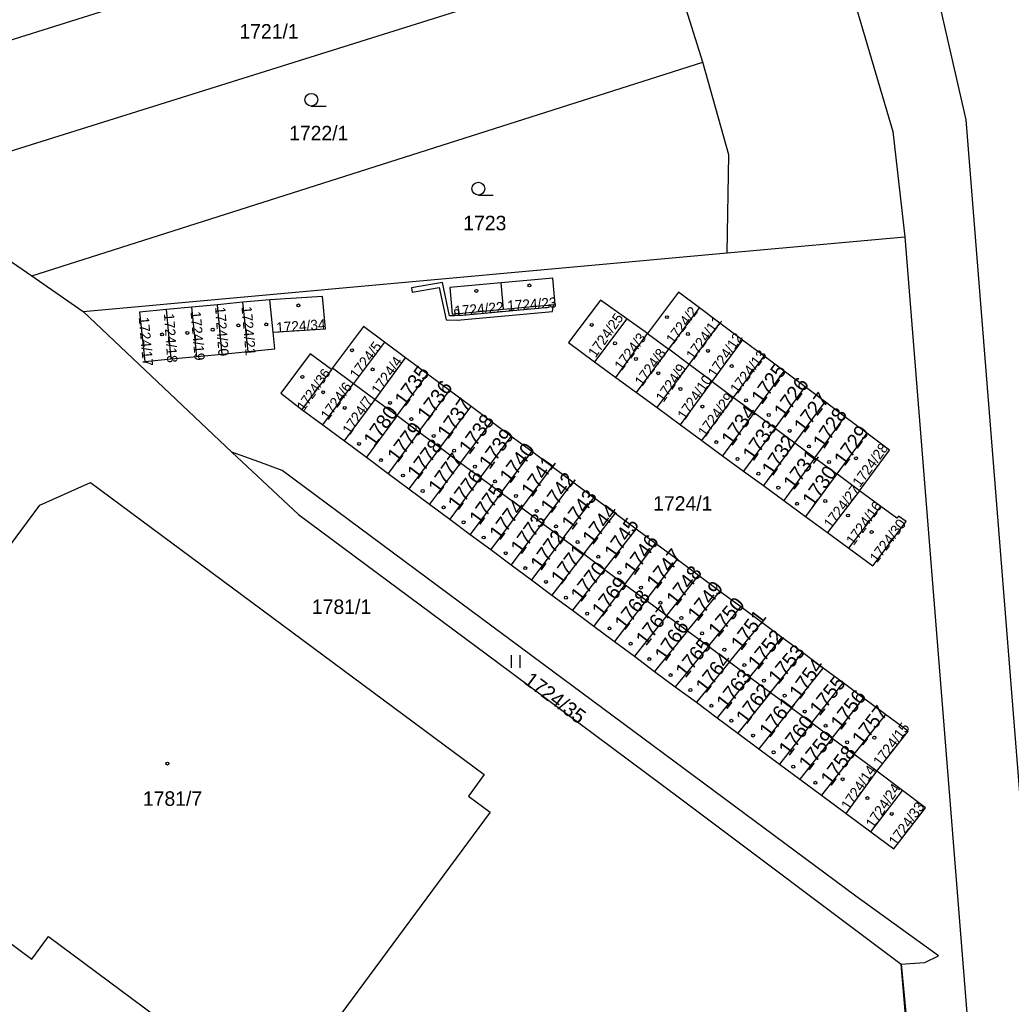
# Model space of a CAD drawing. Extents: x -756746 to -753363, y -1166406 to -1161727.
# Drawn here: x -755865.5 to -755749.2, y -1163941.9 to -1163826.4 of the extents above; entities that cross this region are included whole.
import ezdxf

# ---------------------------------------------------------------- set-up
doc = ezdxf.new("R2010")
doc.units = 0
for name, color, linetype in [('Hranice parcel', 7, 'Continuous'), ('Parcelní čísla', 7, 'Continuous'), ('Věcná břemena k části', 7, 'Continuous'), ('Značky budov', 7, 'Continuous'), ('Značky kultur', 7, 'Continuous')]:
    doc.layers.add(name, color=color, linetype=linetype)

msp = doc.modelspace()

# ---------------------------------------------------------------- linework, layer by layer
at = {"layer": 'Hranice parcel'}
for p, q in [((-755892.36, -1163836.88), (-755793.46, -1163805.8)), ((-755879.46, -1163845.82), (-755796.98, -1163819.99)), ((-755785.34, -1163831.39), (-755788.73, -1163820.69)), ((-755864.11, -1163856.44), (-755785.34, -1163831.39)), ((-755879.46, -1163845.82), (-755864.11, -1163856.44)), ((-755782.49, -1163853.74), (-755761.66, -1163851.85)), ((-755858.09, -1163860.61), (-755782.49, -1163853.74)), ((-755864.11, -1163856.44), (-755858.09, -1163860.61)), ((-755808.73, -1163860.37), (-755809.02, -1163857.25)), ((-755836.15, -1163859.25), (-755839.32, -1163859.55)), ((-755835.77, -1163863.05), (-755836.15, -1163859.25)), ((-755840.62, -1163877.14), (-755858.09, -1163860.61)), ((-755845.31, -1163860.12), (-755848.31, -1163860.41)), ((-755847.74, -1163866.18), (-755848.31, -1163860.41)), ((-755842.32, -1163859.84), (-755845.31, -1163860.12)), ((-755844.75, -1163865.89), (-755845.31, -1163860.12)), ((-755839.32, -1163859.55), (-755842.32, -1163859.84)), ((-755841.78, -1163865.61), (-755842.32, -1163859.84)), ((-755838.72, -1163865.32), (-755839.32, -1163859.55)), ((-755789.36, -1163865.04), (-755785.76, -1163860.2)), ((-755783.36, -1163861.99), (-755785.76, -1163860.2)), ((-755794.29, -1163861.47), (-755798.07, -1163866.51)), ((-755791.84, -1163863.2), (-755794.29, -1163861.47)), ((-755786.96, -1163866.83), (-755783.36, -1163861.99)), ((-755780.7, -1163863.97), (-755783.36, -1163861.99)), ((-755795.57, -1163868.35), (-755791.84, -1163863.2)), ((-755791.84, -1163863.2), (-755789.36, -1163865.04)), ((-755784.26, -1163868.83), (-755780.7, -1163863.97)), ((-755778.16, -1163865.88), (-755780.7, -1163863.97)), ((-755841.78, -1163865.61), (-755838.72, -1163865.32)), ((-755822.73, -1163864.22), (-755826.34, -1163869.06)), ((-755820.25, -1163866.06), (-755822.73, -1163864.22)), ((-755793.14, -1163870.13), (-755789.36, -1163865.04)), ((-755786.96, -1163866.83), (-755789.36, -1163865.04)), ((-755847.74, -1163866.18), (-755844.75, -1163865.89)), ((-755844.75, -1163865.89), (-755841.78, -1163865.61)), ((-755823.82, -1163870.93), (-755820.25, -1163866.06)), ((-755817.66, -1163867.98), (-755820.25, -1163866.06)), ((-755798.07, -1163866.51), (-755795.57, -1163868.35)), ((-755781.74, -1163870.7), (-755778.16, -1163865.88)), ((-755775.8, -1163867.64), (-755778.16, -1163865.88)), ((-755828.94, -1163867.42), (-755832.41, -1163872.1)), ((-755828.8, -1163867.24), (-755828.94, -1163867.42)), ((-755828.8, -1163867.24), (-755826.34, -1163869.06)), ((-755790.73, -1163871.9), (-755786.96, -1163866.83)), ((-755784.26, -1163868.83), (-755786.96, -1163866.83)), ((-755779.34, -1163872.48), (-755775.8, -1163867.64)), ((-755773.34, -1163869.48), (-755775.8, -1163867.64)), ((-755821.24, -1163872.84), (-755817.66, -1163867.98)), ((-755815.08, -1163869.89), (-755817.66, -1163867.98)), ((-755795.57, -1163868.35), (-755793.14, -1163870.13)), ((-755787.99, -1163873.91), (-755784.26, -1163868.83)), ((-755784.26, -1163868.83), (-755781.74, -1163870.7)), ((-755829.96, -1163873.92), (-755826.34, -1163869.06)), ((-755826.34, -1163869.06), (-755823.82, -1163870.93)), ((-755818.68, -1163874.74), (-755815.08, -1163869.89)), ((-755812.54, -1163871.78), (-755815.08, -1163869.89)), ((-755776.88, -1163874.31), (-755773.34, -1163869.48)), ((-755771.01, -1163871.22), (-755773.34, -1163869.48)), ((-755827.41, -1163875.81), (-755823.82, -1163870.93)), ((-755823.82, -1163870.93), (-755821.24, -1163872.84)), ((-755793.14, -1163870.13), (-755790.73, -1163871.9)), ((-755785.49, -1163875.74), (-755781.74, -1163870.7)), ((-755781.74, -1163870.7), (-755779.34, -1163872.48)), ((-755832.41, -1163872.1), (-755829.96, -1163873.92)), ((-755816.18, -1163876.58), (-755812.54, -1163871.78)), ((-755810.15, -1163873.55), (-755812.54, -1163871.78)), ((-755790.73, -1163871.9), (-755787.99, -1163873.91)), ((-755774.55, -1163876.03), (-755771.01, -1163871.22)), ((-755768.68, -1163872.96), (-755771.01, -1163871.22)), ((-755821.24, -1163872.84), (-755824.84, -1163877.72)), ((-755821.24, -1163872.84), (-755818.68, -1163874.74)), ((-755779.34, -1163872.48), (-755783.04, -1163877.54)), ((-755779.34, -1163872.48), (-755776.88, -1163874.31)), ((-755772.2, -1163877.78), (-755768.68, -1163872.96)), ((-755766.1, -1163874.89), (-755768.68, -1163872.96)), ((-755829.96, -1163873.92), (-755827.41, -1163875.81)), ((-755813.78, -1163878.36), (-755810.15, -1163873.55)), ((-755807.83, -1163875.27), (-755810.15, -1163873.55)), ((-755787.99, -1163873.91), (-755785.49, -1163875.74)), ((-755776.88, -1163874.31), (-755780.57, -1163879.35)), ((-755776.88, -1163874.31), (-755774.55, -1163876.03)), ((-755827.41, -1163875.81), (-755824.84, -1163877.72)), ((-755818.68, -1163874.74), (-755822.29, -1163879.61)), ((-755818.68, -1163874.74), (-755816.18, -1163876.58)), ((-755811.43, -1163880.11), (-755807.83, -1163875.27)), ((-755805.44, -1163877.05), (-755807.83, -1163875.27)), ((-755785.49, -1163875.74), (-755783.04, -1163877.54)), ((-755766.1, -1163874.89), (-755769.64, -1163879.68)), ((-755816.18, -1163876.58), (-755819.85, -1163881.42)), ((-755816.18, -1163876.58), (-755813.78, -1163878.36)), ((-755774.55, -1163876.03), (-755778.25, -1163881.05)), ((-755774.55, -1163876.03), (-755772.2, -1163877.78)), ((-755824.84, -1163877.72), (-755822.29, -1163879.61)), ((-755809.03, -1163881.88), (-755805.44, -1163877.05)), ((-755803.02, -1163878.85), (-755805.44, -1163877.05)), ((-755783.04, -1163877.54), (-755780.57, -1163879.35)), ((-755772.2, -1163877.78), (-755775.87, -1163882.79)), ((-755772.2, -1163877.78), (-755769.64, -1163879.68)), ((-755813.78, -1163878.36), (-755817.44, -1163883.21)), ((-755813.78, -1163878.36), (-755811.43, -1163880.11)), ((-755806.61, -1163883.67), (-755803.02, -1163878.85)), ((-755800.6, -1163880.64), (-755803.02, -1163878.85)), ((-755822.29, -1163879.61), (-755819.85, -1163881.42)), ((-755811.43, -1163880.11), (-755815.05, -1163884.98)), ((-755811.43, -1163880.11), (-755809.03, -1163881.88)), ((-755780.57, -1163879.35), (-755778.25, -1163881.05)), ((-755769.64, -1163879.68), (-755773.32, -1163884.67)), ((-755766.99, -1163881.65), (-755769.64, -1163879.68)), ((-755819.85, -1163881.42), (-755817.44, -1163883.21)), ((-755804.2, -1163885.46), (-755800.6, -1163880.64)), ((-755798.13, -1163882.48), (-755800.6, -1163880.64)), ((-755778.25, -1163881.05), (-755775.87, -1163882.79)), ((-755809.03, -1163881.88), (-755812.66, -1163886.76)), ((-755809.03, -1163881.88), (-755806.61, -1163883.67)), ((-755801.78, -1163887.25), (-755798.13, -1163882.48)), ((-755795.65, -1163884.31), (-755798.13, -1163882.48)), ((-755775.87, -1163882.79), (-755773.32, -1163884.67)), ((-755766.99, -1163881.65), (-755770.74, -1163886.56)), ((-755764.48, -1163883.48), (-755766.99, -1163881.65)), ((-755817.44, -1163883.21), (-755815.05, -1163884.98)), ((-755806.61, -1163883.67), (-755810.25, -1163888.55)), ((-755806.61, -1163883.67), (-755804.2, -1163885.46)), ((-755768.24, -1163888.39), (-755764.48, -1163883.48)), ((-755815.05, -1163884.98), (-755812.66, -1163886.76)), ((-755799.33, -1163889.06), (-755795.65, -1163884.31)), ((-755793.19, -1163886.15), (-755795.65, -1163884.31)), ((-755773.32, -1163884.67), (-755770.74, -1163886.56)), ((-755804.2, -1163885.46), (-755807.85, -1163890.33)), ((-755804.2, -1163885.46), (-755801.78, -1163887.25)), ((-755796.9, -1163890.87), (-755793.19, -1163886.15)), ((-755790.92, -1163887.83), (-755793.19, -1163886.15)), ((-755812.66, -1163886.76), (-755810.25, -1163888.55)), ((-755801.78, -1163887.25), (-755805.48, -1163892.09)), ((-755801.78, -1163887.25), (-755799.33, -1163889.06)), ((-755770.74, -1163886.56), (-755768.24, -1163888.39)), ((-755810.25, -1163888.55), (-755807.85, -1163890.33)), ((-755794.51, -1163892.64), (-755790.92, -1163887.83)), ((-755788.35, -1163889.73), (-755790.92, -1163887.83)), ((-755799.33, -1163889.06), (-755803.07, -1163893.88)), ((-755799.33, -1163889.06), (-755796.9, -1163890.87)), ((-755792.01, -1163894.48), (-755788.35, -1163889.73)), ((-755785.88, -1163891.57), (-755788.35, -1163889.73)), ((-755807.85, -1163890.33), (-755805.48, -1163892.09)), ((-755796.9, -1163890.87), (-755800.67, -1163895.66)), ((-755796.9, -1163890.87), (-755794.51, -1163892.64)), ((-755805.48, -1163892.09), (-755803.07, -1163893.88)), ((-755789.6, -1163896.27), (-755785.88, -1163891.57)), ((-755783.35, -1163893.45), (-755785.88, -1163891.57)), ((-755794.51, -1163892.64), (-755798.16, -1163897.52)), ((-755794.51, -1163892.64), (-755792.01, -1163894.48)), ((-755803.07, -1163893.88), (-755800.67, -1163895.66)), ((-755787.14, -1163898.09), (-755783.35, -1163893.45)), ((-755780.91, -1163895.26), (-755783.35, -1163893.45)), ((-755792.01, -1163894.48), (-755795.74, -1163899.32)), ((-755792.01, -1163894.48), (-755789.6, -1163896.27)), ((-755784.71, -1163899.89), (-755780.91, -1163895.26)), ((-755778.42, -1163897.11), (-755780.91, -1163895.26)), ((-755800.67, -1163895.66), (-755798.16, -1163897.52)), ((-755789.6, -1163896.27), (-755793.39, -1163901.06)), ((-755789.6, -1163896.27), (-755787.14, -1163898.09)), ((-755798.16, -1163897.52), (-755795.74, -1163899.32)), ((-755782.23, -1163901.73), (-755778.42, -1163897.11)), ((-755776.08, -1163898.85), (-755778.42, -1163897.11)), ((-755787.14, -1163898.09), (-755791.01, -1163902.83)), ((-755787.14, -1163898.09), (-755784.71, -1163899.89)), ((-755779.83, -1163903.51), (-755776.08, -1163898.85)), ((-755773.68, -1163900.63), (-755776.08, -1163898.85)), ((-755795.74, -1163899.32), (-755793.39, -1163901.06)), ((-755784.71, -1163899.89), (-755788.59, -1163904.63)), ((-755784.71, -1163899.89), (-755782.23, -1163901.73)), ((-755793.39, -1163901.06), (-755791.01, -1163902.83)), ((-755777.42, -1163905.29), (-755773.68, -1163900.63)), ((-755771.23, -1163902.45), (-755773.68, -1163900.63)), ((-755782.23, -1163901.73), (-755786.12, -1163906.46)), ((-755782.23, -1163901.73), (-755779.83, -1163903.51)), ((-755774.96, -1163907.12), (-755771.23, -1163902.45)), ((-755768.89, -1163904.18), (-755771.23, -1163902.45)), ((-755791.01, -1163902.83), (-755788.59, -1163904.63)), ((-755779.83, -1163903.51), (-755783.67, -1163908.28)), ((-755779.83, -1163903.51), (-755777.42, -1163905.29)), ((-755788.59, -1163904.63), (-755786.12, -1163906.46)), ((-755772.57, -1163908.88), (-755768.89, -1163904.18)), ((-755766.49, -1163905.96), (-755768.89, -1163904.18)), ((-755777.42, -1163905.29), (-755781.26, -1163910.07)), ((-755777.42, -1163905.29), (-755774.96, -1163907.12)), ((-755770.18, -1163910.65), (-755766.49, -1163905.96)), ((-755763.93, -1163907.87), (-755766.49, -1163905.96)), ((-755786.12, -1163906.46), (-755783.67, -1163908.28)), ((-755774.96, -1163907.12), (-755778.78, -1163911.91)), ((-755774.96, -1163907.12), (-755772.57, -1163908.88)), ((-755783.67, -1163908.28), (-755781.26, -1163910.07)), ((-755763.93, -1163907.87), (-755767.63, -1163912.54)), ((-755772.57, -1163908.88), (-755776.35, -1163913.71)), ((-755772.57, -1163908.88), (-755770.18, -1163910.65)), ((-755781.26, -1163910.07), (-755778.78, -1163911.91)), ((-755770.18, -1163910.65), (-755773.97, -1163915.47)), ((-755770.18, -1163910.65), (-755767.63, -1163912.54)), ((-755778.78, -1163911.91), (-755776.35, -1163913.71)), ((-755767.63, -1163912.54), (-755771.44, -1163917.36)), ((-755764.92, -1163914.55), (-755767.63, -1163912.54)), ((-755776.35, -1163913.71), (-755773.97, -1163915.47)), ((-755768.55, -1163919.5), (-755764.92, -1163914.55)), ((-755761.92, -1163916.81), (-755764.92, -1163914.55)), ((-755773.97, -1163915.47), (-755771.44, -1163917.36)), ((-755771.44, -1163917.36), (-755768.55, -1163919.5)), ((-755765.66, -1163921.64), (-755761.92, -1163916.81)), ((-755768.55, -1163919.5), (-755765.66, -1163921.64)), ((-755756.36, -1164005.31), (-755762.08, -1163937.18)), ((-755762.08, -1163937.18), (-755753.77, -1164024.87))]:
    msp.add_line(p, q, dxfattribs=at)
for points in [[(-755791.86, -1163751.01), (-755779.82, -1163784.88), (-755772.62, -1163807.19), (-755763.05, -1163839.53), (-755761.66, -1163851.85)], [(-755745.81, -1163946.5), (-755754.44, -1163838.14), (-755759.37, -1163816.57)], [(-755782.49, -1163853.74), (-755782.31, -1163842.27), (-755785.34, -1163831.39)], [(-755761.66, -1163851.85), (-755753.95, -1163948.32), (-755749.42, -1164027.4)], [(-755808.73, -1163860.37), (-755802.68, -1163859.81), (-755802.97, -1163856.7), (-755809.02, -1163857.25)], [(-755809.02, -1163857.25), (-755815.06, -1163857.8), (-755814.78, -1163860.92), (-755808.73, -1163860.37)], [(-755785.76, -1163860.2), (-755788.23, -1163858.35), (-755791.84, -1163863.2)], [(-755835.77, -1163863.05), (-755829.65, -1163862.64), (-755829.97, -1163858.87), (-755836.15, -1163859.25)], [(-755794.29, -1163861.47), (-755797.38, -1163859.28), (-755801.13, -1163864.27), (-755798.07, -1163866.51)], [(-755848.31, -1163860.41), (-755851.47, -1163860.71), (-755850.82, -1163866.47), (-755847.74, -1163866.18)], [(-755822.73, -1163864.22), (-755825.19, -1163862.39), (-755828.8, -1163867.24)], [(-755838.72, -1163865.32), (-755835.58, -1163865.02), (-755835.77, -1163863.05)], [(-755828.94, -1163867.42), (-755831.42, -1163865.59), (-755834.87, -1163870.21), (-755832.41, -1163872.1)], [(-755766.99, -1163881.65), (-755763.45, -1163876.87), (-755766.1, -1163874.89)], [(-755840.62, -1163877.14), (-755832.8, -1163884.43), (-755809.43, -1163901.79), (-755788.08, -1163917.68), (-755762.08, -1163937.18)], [(-755762.08, -1163937.18), (-755761.07, -1163937.11), (-755759.29, -1163936.96), (-755757.71, -1163936.19), (-755767.42, -1163929.2), (-755812.53, -1163895.72), (-755834.74, -1163879.26), (-755837.47, -1163878.24), (-755840.62, -1163877.14)], [(-755889.91, -1163898.92), (-755889.22, -1163898), (-755894.17, -1163894.29), (-755889.13, -1163887.57), (-755874.43, -1163898.52), (-755863.15, -1163883.34), (-755857.21, -1163880.69), (-755811.01, -1163914.93), (-755812.86, -1163917.45), (-755810.31, -1163919.33), (-755827.83, -1163943.04), (-755807.18, -1163958.32), (-755817.15, -1163971.58), (-755812.4, -1163975.09), (-755813.9, -1163977.11)], [(-755768.24, -1163888.39), (-755765.41, -1163890.46), (-755761.5, -1163885.26), (-755762.41, -1163884.61), (-755762.58, -1163884.85), (-755764.48, -1163883.48)], [(-755889.91, -1163898.92), (-755898.81, -1163910.83), (-755864.1, -1163936.57), (-755862.15, -1163933.94), (-755838.26, -1163951.69), (-755835.8, -1163948.4), (-755833.21, -1163950.32), (-755839.11, -1163958.32), (-755813.9, -1163977.11)], [(-755764.92, -1163914.55), (-755761.26, -1163909.85), (-755763.93, -1163907.87)], [(-755765.66, -1163921.64), (-755762.96, -1163923.65), (-755759.21, -1163918.85), (-755761.92, -1163916.81)]]:
    msp.add_lwpolyline(points, dxfattribs=at)
at = {"layer": 'Věcná břemena k části'}
for points in [[(-755819.55, -1163857.85), (-755819.47, -1163858.34), (-755816.29, -1163857.81), (-755815.49, -1163861.6), (-755814.18, -1163861.64), (-755802.98, -1163860.63), (-755802.9, -1163859.83), (-755803.41, -1163859.88), (-755803.44, -1163860.17), (-755813.95, -1163861.12), (-755813.96, -1163860.85), (-755814.46, -1163860.89), (-755814.45, -1163861.13), (-755815.09, -1163861.12), (-755815.89, -1163857.23)], [(-755814.48, -1163860.46), (-755814.46, -1163860.89), (-755813.96, -1163860.85), (-755813.98, -1163860.42)]]:
    msp.add_lwpolyline(points, close=True, dxfattribs=at)
at = {"layer": 'Značky budov'}
for centre in [(-755811.93, -1163858.21), (-755805.7, -1163857.57), (-755832.81, -1163859.91), (-755789.58, -1163861.29), (-755845.85, -1163863.13), (-755842.87, -1163862.76), (-755839.86, -1163862.26), (-755836.59, -1163862.14), (-755798.39, -1163862.2), (-755848.81, -1163863.31), (-755795.67, -1163864.36), (-755787.11, -1163863.27), (-755826.52, -1163865.17), (-755784.76, -1163865.25), (-755793.21, -1163866.19), (-755824.11, -1163867.42), (-755781.97, -1163867.03), (-755832.35, -1163868.3), (-755790.59, -1163867.87), (-755829.91, -1163870.09), (-755787.98, -1163869.71), (-755822.06, -1163871.34), (-755780.28, -1163871.05), (-755827.37, -1163871.93), (-755785.4, -1163871.77), (-755819.56, -1163873.25), (-755777.62, -1163872.76), (-755775.16, -1163874.63), (-755816.94, -1163875.22), (-755783.79, -1163875.94), (-755825.69, -1163876.15), (-755814.55, -1163876.95), (-755772.91, -1163876.45), (-755823.14, -1163878.06), (-755781.29, -1163877.92), (-755770.54, -1163878.28), (-755767.38, -1163877.83), (-755812.11, -1163878.82), (-755820.55, -1163879.86), (-755809.73, -1163880.55), (-755778.83, -1163879.65), (-755818.23, -1163881.68), (-755776.5, -1163881.28), (-755807.29, -1163882.26), (-755771, -1163882.85), (-755815.77, -1163883.6), (-755804.86, -1163884.01), (-755774.3, -1163883.17), (-755768.34, -1163884.55), (-755813.43, -1163885.35), (-755802.59, -1163885.83), (-755811.07, -1163887.13), (-755765.55, -1163886.5), (-755800.06, -1163887.66), (-755808.48, -1163888.97), (-755797.63, -1163889.39), (-755806.2, -1163890.72), (-755795.15, -1163891.27), (-755803.77, -1163892.34), (-755792.61, -1163893), (-755801.43, -1163894.19), (-755790.33, -1163894.78), (-755798.93, -1163896.06), (-755787.88, -1163896.57), (-755796.31, -1163897.79), (-755785.44, -1163898.37), (-755793.83, -1163899.59), (-755782.83, -1163900.28), (-755791.65, -1163901.39), (-755780.49, -1163902.1), (-755789.15, -1163903.27), (-755778.19, -1163903.92), (-755786.81, -1163905.02), (-755775.76, -1163905.68), (-755784.35, -1163906.86), (-755773.39, -1163907.54), (-755782.01, -1163908.63), (-755770.96, -1163909.21), (-755779.46, -1163910.36), (-755765.23, -1163910.6), (-755768.43, -1163911.15), (-755777.05, -1163912.32), (-755848.18, -1163913.64), (-755774.75, -1163914.01), (-755768.96, -1163915.48), (-755772.14, -1163915.89), (-755766.04, -1163917.69), (-755763.18, -1163919.55)]:
    msp.add_circle(centre, 0.175, dxfattribs=at)
at = {"layer": 'Značky kultur'}
for p, q in [((-755831.3, -1163836.54), (-755829.55, -1163836.54)), ((-755811.7, -1163846.97), (-755809.95, -1163846.97)), ((-755807.8, -1163902.43), (-755807.8, -1163900.93)), ((-755806.8, -1163902.43), (-755806.8, -1163900.93))]:
    msp.add_line(p, q, dxfattribs=at)
for centre in [(-755831.3, -1163835.79), (-755811.7, -1163846.22)]:
    msp.add_circle(centre, 0.75, dxfattribs=at)

# ---------------------------------------------------------------- texts
at = {"layer": 'Parcelní čísla'}
for s, p in [('1721/1', (-755839.74, -1163828.62)), ('1722/1', (-755833.91, -1163840.55)), ('1723', (-755813.47, -1163851.1)), ('1724/1', (-755791.19, -1163883.99)), ('1781/1', (-755831.23, -1163896.1)), ('1781/7', (-755851.06, -1163918.6))]:
    msp.add_text(s, height=1.7, dxfattribs=at).set_placement(p)
for s, height, rotation, p in [('1724/22', 1.2, 5, (-755814.46, -1163861.18)), ('1724/23', 1.2, 4, (-755808.27, -1163860.56)), ('1724/20', 1.2, 274, (-755842.59, -1163860.11)), ('1724/21', 1.2, 275, (-755839.5, -1163860.06)), ('1724/2', 1.2, 53, (-755788.82, -1163864.54)), ('1724/17', 1.2, 275, (-755851.56, -1163861.31)), ('1724/18', 1.2, 274, (-755848.6, -1163860.89)), ('1724/19', 1.2, 275, (-755845.48, -1163860.65)), ('1724/34', 1.2, 4, (-755835.38, -1163863.11)), ('1724/25', 1.2, 55, (-755797.94, -1163866.12)), ('1724/11', 1.2, 54, (-755786.45, -1163866.4)), ('1724/5', 1.2, 53, (-755825.92, -1163868.65)), ('1724/3', 1.2, 53, (-755794.88, -1163867.64)), ('1724/12', 1.2, 56, (-755783.87, -1163868.46)), ('1724/8', 1.2, 54, (-755792.48, -1163869.49)), ('1724/13', 1.2, 53, (-755781.29, -1163870.35)), ('1724/4', 1.2, 55, (-755823.37, -1163870.47)), ('1724/36', 1.139, 55, (-755832.16, -1163872.36)), ('1735', 1.7, 54, (-755820.3, -1163871.88)), ('1724/9', 1.2, 56, (-755789.97, -1163871.36)), ('1725', 1.7, 54, (-755778.44, -1163871.64)), ('1736', 1.7, 53, (-755817.67, -1163873.58)), ('1724/10', 1.2, 56, (-755787.45, -1163873.42)), ('1726', 1.7, 54, (-755775.8, -1163873.24)), ('1724/6', 1.2, 54, (-755829.33, -1163873.44)), ('1727', 1.7, 53, (-755773.47, -1163874.98)), ('1724/7', 1.2, 56, (-755826.76, -1163875.16)), ('1737', 1.7, 55, (-755815.26, -1163875.7)), ('1724/29', 1.2, 54, (-755785.06, -1163875.42)), ('1780', 1.7, 55, (-755823.93, -1163876.6)), ('1734', 1.7, 54, (-755781.95, -1163876.51)), ('1728', 1.7, 56, (-755771.17, -1163876.85)), ('1738', 1.7, 53, (-755812.77, -1163877.51)), ('1733', 1.7, 55, (-755779.44, -1163878.27)), ('1779', 1.7, 53, (-755821.18, -1163878.46)), ('1739', 1.7, 54, (-755810.39, -1163879.25)), ('1729', 1.7, 54, (-755768.73, -1163878.87)), ('1778', 1.7, 53, (-755818.84, -1163880.44)), ('1732', 1.7, 56, (-755777.17, -1163880.03)), ('1740', 1.7, 53, (-755807.99, -1163880.9)), ('1724/28', 1.2, 54, (-755766.93, -1163881.32)), ('1777', 1.7, 54, (-755816.35, -1163882.12)), ('1741', 1.7, 55, (-755805.42, -1163882.5)), ('1731', 1.7, 53, (-755774.7, -1163881.67)), ('1776', 1.7, 53, (-755814.08, -1163884.04)), ('1730', 1.7, 55, (-755772.43, -1163883.63)), ('1742', 1.7, 54, (-755803.16, -1163884.4)), ('1775', 1.7, 54, (-755811.55, -1163885.78)), ('1743', 1.7, 53, (-755800.72, -1163886.37)), ('1724/27', 1.2, 53, (-755770.33, -1163886.17)), ('1774', 1.7, 53, (-755809.2, -1163887.57)), ('1744', 1.7, 53, (-755798.28, -1163888.1)), ('1724/16', 1.2, 54, (-755767.66, -1163888.14)), ('1773', 1.7, 54, (-755806.68, -1163889.22)), ('1745', 1.7, 55, (-755795.67, -1163889.76)), ('1724/30', 1.2, 53, (-755764.93, -1163890.18)), ('1772', 1.7, 54, (-755804.36, -1163891.13)), ('1746', 1.7, 54, (-755793.41, -1163891.68)), ('1771', 1.7, 53, (-755801.99, -1163892.78)), ('1747', 1.7, 52, (-755790.79, -1163893.29)), ('1770', 1.7, 52, (-755799.68, -1163894.8)), ('1748', 1.7, 52, (-755788.47, -1163895.27)), ('1769', 1.7, 52, (-755797.2, -1163896.56)), ('1749', 1.7, 52, (-755785.97, -1163897.07)), ('1768', 1.7, 52, (-755794.54, -1163898.1)), ('1750', 1.7, 50, (-755783.58, -1163898.92)), ('1767', 1.7, 52, (-755792.04, -1163899.95)), ('1751', 1.7, 53, (-755780.86, -1163900.5)), ('1766', 1.7, 56, (-755789.73, -1163901.77)), ('1765', 1.7, 51, (-755787.41, -1163903.71)), ('1752', 1.7, 51, (-755778.91, -1163902.75)), ('1753', 1.7, 50, (-755776.53, -1163904.47)), ('1764', 1.7, 52, (-755785.01, -1163905.49)), ('1754', 1.7, 54, (-755773.99, -1163906.22)), ('1724/35', 1.7, 323, (-755806.48, -1163904.14)), ('1763', 1.7, 52, (-755782.58, -1163907.4)), ('1755', 1.7, 51, (-755771.67, -1163908.16)), ('1762', 1.7, 53, (-755780.25, -1163909.14)), ('1761', 1.7, 53, (-755777.52, -1163910.71)), ('1756', 1.7, 52, (-755769.19, -1163909.82)), ('1757', 1.7, 52, (-755766.66, -1163911.67)), ('1760', 1.7, 53, (-755775.24, -1163912.85)), ('1724/15', 1.2, 53, (-755764.51, -1163914.06)), ('1759', 1.7, 51, (-755772.94, -1163914.56)), ('1758', 1.7, 53, (-755770.33, -1163916.38)), ('1724/14', 1.2, 56, (-755768.22, -1163919.19)), ('1724/24', 1.2, 56, (-755765.35, -1163921.32)), ('1724/33', 1.2, 54, (-755762.68, -1163923.39))]:
    msp.add_text(s, height=height, rotation=rotation, dxfattribs=at).set_placement(p)

doc.saveas('drawing.dxf')
